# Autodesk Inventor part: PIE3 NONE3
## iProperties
Shininess: 64.0
Length Units: 11269
Angle Units: 11279
Time Units: 11290
Mass Units: 11286
Length Display Precision: 3
Angle Display Precision: 2
Compacted: True
Part Number: PIE3 NONE3
Document SubType Name: Modeling
Created: 2004-08
Designer: John Blackburn
Manufacturer: Standard
Standards Organization: Custom
Density: 0.0
Volumn: 0.0
Area: 0.0
PropertySet Name: Model Information
Control State: 0
Master: False
Checked Out: False
Author: John Blackburn
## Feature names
1. Erst1
